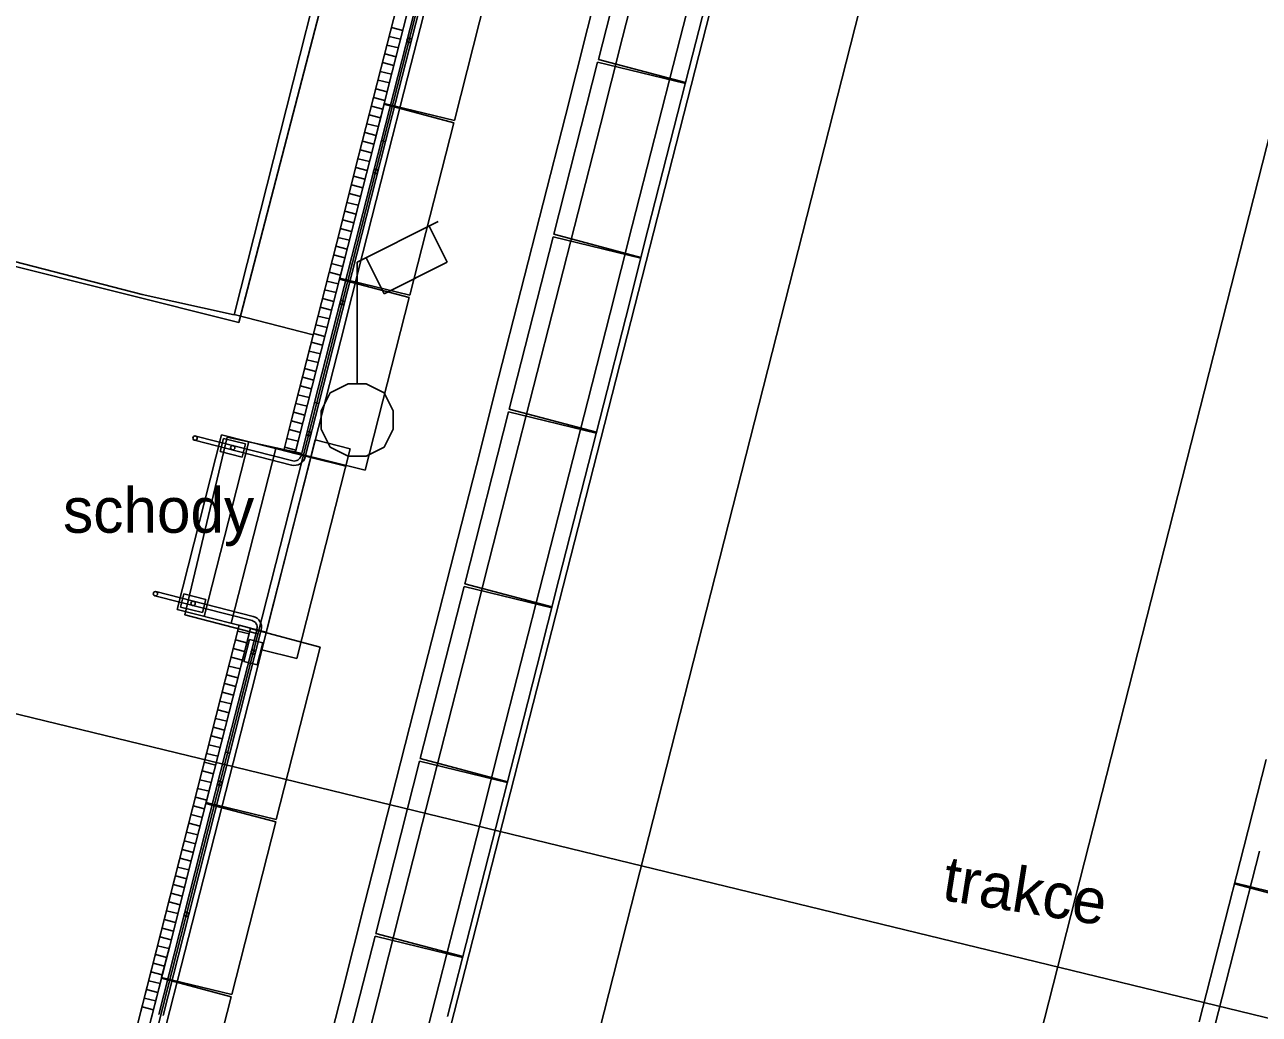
# Model space of a CAD drawing. Extents: x -733601 to -733291, y -1137892 to -1137187.
# Drawn here: x -733465.26 to -733451.57, y -1137693.72 to -1137682.75 of the extents above; entities that cross this region are included whole.
import ezdxf

# ---------------------------------------------------------------- set-up
doc = ezdxf.new("R2010")
doc.units = 0
doc.layers.add('SIT_PUV_BUS', color=7, linetype='Continuous')
doc.layers.add('SIT_PUV_ZELEZNICE', color=7, linetype='Continuous')

msp = doc.modelspace()

# ---------------------------------------------------------------- linework, layer by layer
at = {"layer": 'SIT_PUV_BUS'}
for p, q in [((-733452.43, -1137662.15), (-733466.53, -1137717.32)), ((-733461.23, -1137679.7), (-733462.88, -1137686.05)), ((-733460.18, -1137679.73), (-733469.47, -1137716.2)), ((-733462.88, -1137686.05), (-733470.52, -1137684.13)), ((-733461.57, -1137685.38), (-733460.67, -1137684.93)), ((-733460.77, -1137684.98), (-733460.57, -1137685.38)), ((-733461.57, -1137686.73), (-733461.57, -1137685.38)), ((-733461.27, -1137685.73), (-733461.47, -1137685.33)), ((-733460.57, -1137685.38), (-733461.27, -1137685.73)), ((-733461.97, -1137687.03), (-733461.87, -1137686.83)), ((-733461.87, -1137686.83), (-733461.67, -1137686.73)), ((-733461.67, -1137686.73), (-733461.47, -1137686.73)), ((-733461.47, -1137686.73), (-733461.27, -1137686.83)), ((-733461.27, -1137686.83), (-733461.17, -1137687.03)), ((-733461.97, -1137687.23), (-733461.97, -1137687.03)), ((-733461.17, -1137687.03), (-733461.17, -1137687.23)), ((-733461.87, -1137687.43), (-733461.97, -1137687.23)), ((-733461.17, -1137687.23), (-733461.27, -1137687.43)), ((-733463.01, -1137687.32), (-733463.48, -1137689.29)), ((-733462.18, -1137687.5), (-733463.01, -1137687.32)), ((-733461.67, -1137687.53), (-733461.87, -1137687.43)), ((-733461.27, -1137687.43), (-733461.47, -1137687.53)), ((-733461.47, -1137687.53), (-733461.67, -1137687.53)), ((-733463.48, -1137689.29), (-733462.67, -1137689.5)), ((-733465.63, -1137690.32), (-733451.03, -1137693.87))]:
    msp.add_line(p, q, dxfattribs=at)
at = {"layer": 'SIT_PUV_ZELEZNICE'}
for p, q in [((-733461.3, -1137684.029), (-733460.56, -1137681.122)), ((-733461.254, -1137684.041), (-733460.513, -1137681.134)), ((-733458.409, -1137681.223), (-733458.895, -1137683.132)), ((-733460.004, -1137681.896), (-733460.492, -1137683.809)), ((-733461.063, -1137682.811), (-733461.189, -1137682.779)), ((-733461.113, -1137683.005), (-733461.239, -1137682.973)), ((-733461.088, -1137682.908), (-733461.214, -1137682.876)), ((-733461.137, -1137683.102), (-733461.263, -1137683.07)), ((-733458.895, -1137683.132), (-733457.929, -1137683.389)), ((-733461.187, -1137683.296), (-733461.313, -1137683.264)), ((-733461.162, -1137683.199), (-733461.288, -1137683.167)), ((-733458.903, -1137683.161), (-733459.389, -1137685.07)), ((-733457.931, -1137683.399), (-733458.903, -1137683.161)), ((-733461.211, -1137683.393), (-733461.337, -1137683.361)), ((-733461.236, -1137683.49), (-733461.362, -1137683.457)), ((-733461.285, -1137683.683), (-733461.411, -1137683.651)), ((-733461.261, -1137683.586), (-733461.387, -1137683.554)), ((-733461.271, -1137683.629), (-733460.498, -1137683.834)), ((-733460.492, -1137683.809), (-733461.269, -1137683.619)), ((-733461.31, -1137683.78), (-733461.436, -1137683.748)), ((-733461.359, -1137683.974), (-733461.485, -1137683.942)), ((-733461.335, -1137683.877), (-733461.461, -1137683.845)), ((-733460.498, -1137683.834), (-733460.985, -1137685.747)), ((-733462.041, -1137686.936), (-733461.3, -1137684.029)), ((-733461.994, -1137686.948), (-733461.254, -1137684.041)), ((-733461.384, -1137684.071), (-733461.51, -1137684.039)), ((-733461.3, -1137684.029), (-733461.254, -1137684.041)), ((-733461.254, -1137684.041), (-733461.3, -1137684.029)), ((-733461.433, -1137684.265), (-733461.559, -1137684.233)), ((-733461.409, -1137684.168), (-733461.535, -1137684.136)), ((-733461.458, -1137684.362), (-733461.584, -1137684.33)), ((-733461.483, -1137684.459), (-733461.609, -1137684.427)), ((-733461.532, -1137684.652), (-733461.658, -1137684.62)), ((-733461.508, -1137684.555), (-733461.634, -1137684.523)), ((-733461.557, -1137684.749), (-733461.683, -1137684.717)), ((-733461.606, -1137684.943), (-733461.732, -1137684.911)), ((-733461.582, -1137684.846), (-733461.708, -1137684.814)), ((-733461.631, -1137685.04), (-733461.757, -1137685.008)), ((-733461.656, -1137685.137), (-733461.782, -1137685.105)), ((-733459.396, -1137685.1), (-733459.883, -1137687.009)), ((-733458.425, -1137685.337), (-733459.396, -1137685.1)), ((-733459.389, -1137685.07), (-733458.423, -1137685.327)), ((-733461.705, -1137685.331), (-733461.831, -1137685.299)), ((-733461.68, -1137685.234), (-733461.806, -1137685.202)), ((-733461.73, -1137685.428), (-733461.856, -1137685.396)), ((-733461.779, -1137685.621), (-733461.905, -1137685.589)), ((-733461.754, -1137685.525), (-733461.88, -1137685.492)), ((-733461.765, -1137685.567), (-733460.992, -1137685.772)), ((-733460.985, -1137685.747), (-733461.763, -1137685.557)), ((-733461.804, -1137685.718), (-733461.93, -1137685.686)), ((-733461.828, -1137685.815), (-733461.954, -1137685.783)), ((-733460.992, -1137685.772), (-733461.479, -1137687.685)), ((-733462.934, -1137685.959), (-733462.057, -1137686.185)), ((-733461.878, -1137686.009), (-733462.004, -1137685.977)), ((-733461.853, -1137685.912), (-733461.979, -1137685.88)), ((-733461.902, -1137686.106), (-733462.028, -1137686.074)), ((-733461.952, -1137686.3), (-733462.078, -1137686.268)), ((-733461.927, -1137686.203), (-733462.053, -1137686.171)), ((-733461.977, -1137686.397), (-733462.103, -1137686.365)), ((-733462.026, -1137686.591), (-733462.152, -1137686.558)), ((-733462.001, -1137686.494), (-733462.127, -1137686.462)), ((-733462.051, -1137686.687), (-733462.177, -1137686.655)), ((-733462.075, -1137686.784), (-733462.201, -1137686.752)), ((-733462.125, -1137686.978), (-733462.251, -1137686.946)), ((-733462.1, -1137686.881), (-733462.226, -1137686.849)), ((-733462.041, -1137686.936), (-733462.191, -1137687.527)), ((-733461.994, -1137686.948), (-733462.145, -1137687.539)), ((-733462.041, -1137686.936), (-733461.994, -1137686.948)), ((-733462.041, -1137686.936), (-733461.994, -1137686.948)), ((-733462.149, -1137687.075), (-733462.275, -1137687.043)), ((-733459.89, -1137687.038), (-733460.377, -1137688.947)), ((-733458.919, -1137687.275), (-733459.89, -1137687.038)), ((-733459.883, -1137687.009), (-733458.916, -1137687.265)), ((-733462.199, -1137687.269), (-733462.325, -1137687.237)), ((-733462.174, -1137687.172), (-733462.3, -1137687.14)), ((-733462.296, -1137687.629), (-733463.372, -1137687.355)), ((-733462.284, -1137687.582), (-733463.36, -1137687.308)), ((-733463.051, -1137687.334), (-733463.088, -1137687.479)), ((-733462.258, -1137687.5), (-733463.072, -1137687.293)), ((-733462.809, -1137687.396), (-733463.051, -1137687.334)), ((-733462.034, -1137687.351), (-733462.626, -1137689.677)), ((-733462.223, -1137687.366), (-733462.349, -1137687.334)), ((-733461.646, -1137687.45), (-733462.034, -1137687.351)), ((-733463.088, -1137687.479), (-733462.846, -1137687.541)), ((-733462.846, -1137687.541), (-733462.809, -1137687.396)), ((-733462.248, -1137687.463), (-733462.374, -1137687.431)), ((-733462.258, -1137687.5), (-733462.083, -1137687.545)), ((-733461.479, -1137687.685), (-733462.256, -1137687.495)), ((-733462.239, -1137689.775), (-733461.646, -1137687.45)), ((-733461.696, -1137687.643), (-733462.083, -1137687.545)), ((-733460.384, -1137688.976), (-733460.87, -1137690.885)), ((-733459.412, -1137689.213), (-733460.384, -1137688.976)), ((-733460.377, -1137688.947), (-733459.41, -1137689.203)), ((-733462.735, -1137689.354), (-733463.811, -1137689.08)), ((-733462.723, -1137689.307), (-733463.8, -1137689.033)), ((-733463.528, -1137689.204), (-733463.491, -1137689.059)), ((-733463.491, -1137689.059), (-733463.248, -1137689.121)), ((-733463.248, -1137689.121), (-733463.285, -1137689.266)), ((-733462.751, -1137689.438), (-733463.565, -1137689.231)), ((-733463.285, -1137689.266), (-733463.528, -1137689.204)), ((-733463.028, -1137690.812), (-733462.68, -1137689.446)), ((-733462.982, -1137690.824), (-733462.633, -1137689.458)), ((-733462.792, -1137689.599), (-733462.918, -1137689.567)), ((-733462.768, -1137689.502), (-733462.894, -1137689.47)), ((-733462.825, -1137689.807), (-733462.763, -1137689.564)), ((-733462.763, -1137689.564), (-733462.617, -1137689.601)), ((-733462.753, -1137689.443), (-733461.979, -1137689.648)), ((-733462.751, -1137689.438), (-733462.577, -1137689.483)), ((-733462.817, -1137689.696), (-733462.943, -1137689.664)), ((-733462.617, -1137689.601), (-733462.679, -1137689.844)), ((-733462.626, -1137689.677), (-733462.239, -1137689.775)), ((-733461.979, -1137689.648), (-733462.467, -1137691.561)), ((-733462.842, -1137689.793), (-733462.968, -1137689.761)), ((-733462.679, -1137689.844), (-733462.825, -1137689.807)), ((-733462.891, -1137689.987), (-733463.017, -1137689.955)), ((-733462.866, -1137689.89), (-733462.992, -1137689.858)), ((-733462.916, -1137690.084), (-733463.042, -1137690.052)), ((-733462.965, -1137690.278), (-733463.091, -1137690.246)), ((-733462.94, -1137690.181), (-733463.066, -1137690.149)), ((-733462.99, -1137690.375), (-733463.116, -1137690.342)), ((-733463.015, -1137690.471), (-733463.141, -1137690.439)), ((-733463.064, -1137690.665), (-733463.19, -1137690.633)), ((-733463.039, -1137690.568), (-733463.165, -1137690.536)), ((-733463.089, -1137690.762), (-733463.215, -1137690.73)), ((-733463.769, -1137693.72), (-733463.028, -1137690.812)), ((-733463.722, -1137693.732), (-733462.982, -1137690.824)), ((-733463.138, -1137690.956), (-733463.264, -1137690.924)), ((-733463.113, -1137690.859), (-733463.239, -1137690.827)), ((-733462.982, -1137690.824), (-733463.028, -1137690.812)), ((-733463.028, -1137690.812), (-733462.982, -1137690.824)), ((-733460.878, -1137690.914), (-733461.364, -1137692.823)), ((-733459.906, -1137691.151), (-733460.878, -1137690.914)), ((-733460.87, -1137690.885), (-733459.904, -1137691.141)), ((-733463.163, -1137691.053), (-733463.289, -1137691.021)), ((-733463.212, -1137691.247), (-733463.338, -1137691.215)), ((-733463.187, -1137691.15), (-733463.313, -1137691.118)), ((-733463.237, -1137691.344), (-733463.363, -1137691.312)), ((-733463.261, -1137691.44), (-733463.387, -1137691.408)), ((-733463.246, -1137691.381), (-733462.473, -1137691.586)), ((-733462.467, -1137691.561), (-733463.244, -1137691.372)), ((-733463.311, -1137691.634), (-733463.437, -1137691.602)), ((-733463.286, -1137691.537), (-733463.412, -1137691.505)), ((-733462.473, -1137691.586), (-733462.96, -1137693.499)), ((-733463.335, -1137691.731), (-733463.461, -1137691.699)), ((-733463.385, -1137691.925), (-733463.511, -1137691.893)), ((-733463.36, -1137691.828), (-733463.486, -1137691.796)), ((-733463.41, -1137692.022), (-733463.536, -1137691.99)), ((-733463.434, -1137692.119), (-733463.56, -1137692.087)), ((-733463.484, -1137692.313), (-733463.61, -1137692.281)), ((-733463.459, -1137692.216), (-733463.585, -1137692.184)), ((-733451.843, -1137692.273), (-733450.877, -1137692.529)), ((-733450.869, -1137692.5), (-733451.841, -1137692.263)), ((-733463.508, -1137692.41), (-733463.634, -1137692.377)), ((-733463.558, -1137692.603), (-733463.684, -1137692.571)), ((-733463.533, -1137692.506), (-733463.659, -1137692.474)), ((-733463.582, -1137692.7), (-733463.708, -1137692.668)), ((-733463.607, -1137692.797), (-733463.733, -1137692.765)), ((-733461.371, -1137692.852), (-733461.858, -1137694.761)), ((-733460.4, -1137693.089), (-733461.371, -1137692.852)), ((-733461.364, -1137692.823), (-733460.397, -1137693.079)), ((-733463.656, -1137692.991), (-733463.782, -1137692.959)), ((-733463.632, -1137692.894), (-733463.758, -1137692.862)), ((-733463.681, -1137693.088), (-733463.807, -1137693.056)), ((-733463.73, -1137693.282), (-733463.856, -1137693.25)), ((-733463.706, -1137693.185), (-733463.832, -1137693.153)), ((-733463.755, -1137693.379), (-733463.881, -1137693.347)), ((-733463.74, -1137693.319), (-733462.967, -1137693.525)), ((-733462.96, -1137693.499), (-733463.738, -1137693.31)), ((-733463.804, -1137693.572), (-733463.93, -1137693.54)), ((-733463.78, -1137693.476), (-733463.906, -1137693.443)), ((-733462.967, -1137693.525), (-733463.454, -1137695.437)), ((-733463.829, -1137693.669), (-733463.955, -1137693.637))]:
    msp.add_line(p, q, dxfattribs=at)
for points in [[(-733469.582, -1137755.14), (-733468.663, -1137751.534), (-733466.195, -1137741.843), (-733463.726, -1137732.153), (-733461.257, -1137722.462), (-733458.789, -1137712.772), (-733456.32, -1137703.081), (-733453.852, -1137693.391), (-733451.383, -1137683.701), (-733451.044, -1137682.371), (-733448.914, -1137674.01), (-733446.443, -1137664.32), (-733443.966, -1137654.632), (-733441.48, -1137644.946), (-733438.982, -1137635.263), (-733436.47, -1137625.584), (-733433.94, -1137615.909), (-733431.39, -1137606.239), (-733431.038, -1137604.913), (-733428.815, -1137596.577), (-733426.217, -1137586.92), (-733424.808, -1137581.736)], [(-733473.591, -1137751.638), (-733472.603, -1137747.76), (-733470.135, -1137738.069), (-733467.666, -1137728.379), (-733465.198, -1137718.688), (-733462.729, -1137708.998), (-733460.26, -1137699.307), (-733457.792, -1137689.617), (-733455.323, -1137679.926), (-733452.855, -1137670.236), (-733450.386, -1137660.545), (-733448.734, -1137654.061), (-733447.917, -1137650.855), (-733445.432, -1137641.168), (-733442.928, -1137631.487), (-733440.405, -1137621.811), (-733437.862, -1137612.139), (-733437.8, -1137611.906), (-733435.314, -1137602.469), (-733432.775, -1137592.797), (-733432.613, -1137592.177)], [(-733462.935, -1137685.963), (-733461.332, -1137679.64), (-733453.759, -1137650.014), (-733456.593, -1137649.288), (-733465.899, -1137646.951)], [(-733462.935, -1137685.963), (-733463.955, -1137685.738), (-733470.522, -1137684.041), (-733469.12, -1137678.024), (-733473.546, -1137676.915), (-733475.039, -1137682.876), (-733475.39, -1137682.788)], [(-733461.976, -1137694.417), (-733461.73, -1137693.448), (-733461.483, -1137692.479), (-733461.236, -1137691.51), (-733460.989, -1137690.541), (-733460.742, -1137689.572), (-733460.495, -1137688.603), (-733460.248, -1137687.634), (-733460.002, -1137686.664), (-733459.755, -1137685.695), (-733459.508, -1137684.726), (-733459.261, -1137683.757), (-733459.014, -1137682.788), (-733458.767, -1137681.819)], [(-733461.589, -1137694.516), (-733461.342, -1137693.547), (-733461.095, -1137692.578), (-733460.848, -1137691.608), (-733460.601, -1137690.639), (-733460.354, -1137689.67), (-733460.108, -1137688.701), (-733459.861, -1137687.732), (-733459.614, -1137686.763), (-733459.367, -1137685.794), (-733459.12, -1137684.825), (-733458.873, -1137683.856), (-733458.626, -1137682.887), (-733458.38, -1137681.918)], [(-733460.988, -1137694.669), (-733460.741, -1137693.7), (-733460.494, -1137692.731), (-733460.247, -1137691.762), (-733460.001, -1137690.792), (-733459.754, -1137689.823), (-733459.507, -1137688.854), (-733459.26, -1137687.885), (-733459.013, -1137686.916), (-733458.766, -1137685.947), (-733458.519, -1137684.978), (-733458.273, -1137684.009), (-733458.026, -1137683.04), (-733457.779, -1137682.071)], [(-733460.567, -1137693.744), (-733460.32, -1137692.775), (-733460.073, -1137691.806), (-733459.826, -1137690.837), (-733459.579, -1137689.868), (-733459.332, -1137688.899), (-733459.086, -1137687.93), (-733458.839, -1137686.961), (-733458.592, -1137685.992), (-733458.345, -1137685.023), (-733458.098, -1137684.054), (-733457.851, -1137683.084), (-733457.604, -1137682.115)], [(-733462.384, -1137687.468), (-733462.293, -1137687.113), (-733462.046, -1137686.144), (-733461.799, -1137685.175), (-733461.553, -1137684.206), (-733461.306, -1137683.236), (-733461.059, -1137682.267)], [(-733461.059, -1137682.267), (-733461.306, -1137683.236), (-733461.553, -1137684.206), (-733461.799, -1137685.175), (-733462.046, -1137686.144), (-733462.058, -1137686.189), (-733462.293, -1137687.113), (-733462.384, -1137687.468), (-733462.258, -1137687.5), (-733462.256, -1137687.495), (-733462.167, -1137687.145), (-733461.92, -1137686.176), (-733461.765, -1137685.567), (-733461.763, -1137685.557), (-733461.673, -1137685.207), (-733461.427, -1137684.238), (-733461.271, -1137683.629), (-733461.269, -1137683.619), (-733461.18, -1137683.269), (-733460.933, -1137682.299)], [(-733462.258, -1137687.5), (-733462.167, -1137687.145), (-733461.92, -1137686.176), (-733461.673, -1137685.207), (-733461.427, -1137684.238), (-733461.18, -1137683.269), (-733460.933, -1137682.299)], [(-733463.727, -1137693.996), (-733463.48, -1137693.027), (-733463.233, -1137692.058), (-733462.986, -1137691.089), (-733462.739, -1137690.12), (-733462.492, -1137689.151), (-733462.246, -1137688.182), (-733461.999, -1137687.213), (-733461.752, -1137686.244), (-733461.505, -1137685.275), (-733461.258, -1137684.306), (-733461.011, -1137683.337), (-733460.764, -1137682.368)], [(-733463.565, -1137689.231), (-733463.072, -1137687.293)], [(-733463.265, -1137689.307), (-733462.771, -1137687.369)], [(-733462.965, -1137689.384), (-733462.471, -1137687.446)], [(-733469.666, -1137716.055), (-733462.877, -1137689.406)], [(-733463.895, -1137693.928), (-733463.648, -1137692.959), (-733463.401, -1137691.99), (-733463.155, -1137691.021), (-733462.908, -1137690.052), (-733462.751, -1137689.438)], [(-733452.233, -1137693.803), (-733451.986, -1137692.834), (-733451.74, -1137691.865), (-733451.493, -1137690.896)], [(-733452.059, -1137693.847), (-733451.812, -1137692.878), (-733451.565, -1137691.909)]]:
    msp.add_lwpolyline(points, dxfattribs=at)
msp.add_lwpolyline([(-733462.751, -1137689.438), (-733462.877, -1137689.406), (-733464.852, -1137697.159), (-733464.726, -1137697.191), (-733464.725, -1137697.186), (-733464.636, -1137696.835), (-733464.389, -1137695.866), (-733464.234, -1137695.257), (-733464.231, -1137695.248), (-733464.142, -1137694.897), (-733463.895, -1137693.928), (-733463.74, -1137693.319), (-733463.738, -1137693.31), (-733463.648, -1137692.959), (-733463.401, -1137691.99), (-733463.246, -1137691.381), (-733463.244, -1137691.372), (-733463.155, -1137691.021), (-733462.908, -1137690.052), (-733462.753, -1137689.443)], close=True, dxfattribs=at)
for centre in [(-733460.993, -1137682.921), (-733461.363, -1137684.374), (-733461.734, -1137685.828), (-733463.366, -1137687.331), (-733462.104, -1137687.281), (-733462.949, -1137687.438), (-733463.806, -1137689.056), (-733463.388, -1137689.163), (-733462.721, -1137689.704), (-733463.091, -1137691.158), (-733463.462, -1137692.611)]:
    msp.add_circle(centre, 0.0241, dxfattribs=at)
for centre, radius, start, end in [((-733462.265, -1137687.509), 0.124, 255.7084, 345.7084), ((-733462.265, -1137687.509), 0.0758, 255.7084, 345.7084), ((-733462.754, -1137689.427), 0.0759, 345.7084, 75.7084), ((-733462.754, -1137689.427), 0.124, 345.7084, 75.7084)]:
    msp.add_arc(centre, radius, start, end, dxfattribs=at)

# ---------------------------------------------------------------- texts
at = {"layer": 'SIT_PUV_BUS'}
msp.add_text('schody', height=0.5, dxfattribs=at).set_placement((-733464.83, -1137688.38))
msp.add_text('trakce', height=0.5, rotation=351, dxfattribs=at).set_placement((-733455.1, -1137692.45))

doc.saveas('drawing.dxf')
